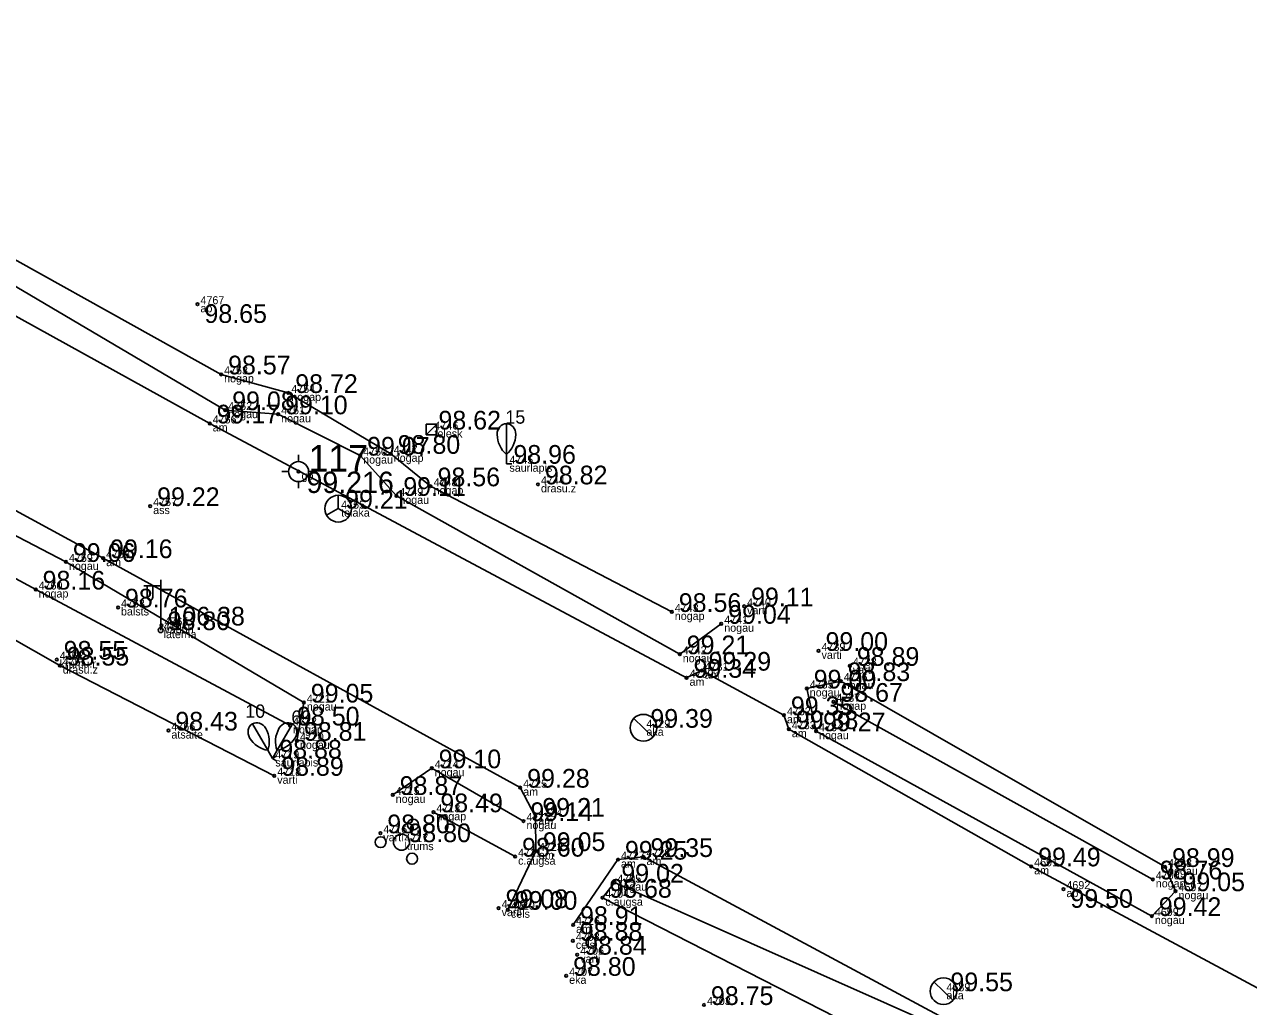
# Model space of a CAD drawing. Extents: x 614911 to 615803, y 262110 to 264311.
# Drawn here: x 615424.61 to 615470.48, y 264009.08 to 264045.87 of the extents above; entities that cross this region are included whole.
import ezdxf

# ---------------------------------------------------------------- set-up
doc = ezdxf.new("R2010")
doc.units = 0
for name, color, linetype in [('Level 1', 7, 'Continuous'), ('Level 12', 7, 'Continuous'), ('Level 19', 7, 'Continuous'), ('Level 31', 7, 'Continuous'), ('Level 35', 7, 'Continuous'), ('Level 37', 7, 'Continuous'), ('Level 44', 7, 'Continuous'), ('Level 49', 7, 'Continuous'), ('Level 53', 7, 'Continuous'), ('Level 54', 7, 'Continuous'), ('Level 57', 7, 'Continuous'), ('Level 58', 7, 'Continuous')]:
    doc.layers.add(name, color=color, linetype=linetype)

msp = doc.modelspace()

# ---------------------------------------------------------------- linework, layer by layer
at = {"layer": 'Level 1'}
for p, q in [((615442.676, 264029.765), (615442.676, 264029.413)), ((615442.676, 264029.413), (615442.876, 264029.413)), ((615433.728, 264018.676), (615433.904, 264018.371)), ((615434.08, 264018.676), (615433.904, 264018.371)), ((615433.904, 264018.371), (615434.077, 264018.471)), ((615433.904, 264018.371), (615434.077, 264018.271))]:
    msp.add_line(p, q, dxfattribs=at)
for points in [[(615442.676, 264030.913), (615442.676, 264029.765)], [(615433.154, 264019.67), (615433.728, 264018.676)], [(615434.654, 264019.67), (615434.08, 264018.676)]]:
    msp.add_lwpolyline(points, dxfattribs=at)
for centre, radius in [((615439.17, 264015.896), 0.207), ((615437.959, 264015.236), 0.204), ((615438.743, 264015.236), 0.301), ((615439.138, 264014.616), 0.205)]:
    msp.add_circle(centre, radius, dxfattribs=at)
for centre, major_axis, start_param, end_param in [((615442.676, 264030.513), (0, 0.4), 0, 1.570796), ((615442.676, 264030.513), (0, -0.4), 1.570796, 3.141593), ((615443.151, 264030.536), (0, -0.943), 4.7372, 5.669711), ((615442.201, 264030.536), (0, -0.943), 0.613474, 1.545985), ((615433.354, 264019.324), (-0.2, 0.346), 0, 1.570796), ((615433.354, 264019.324), (0.2, -0.346), 1.570796, 3.141593), ((615432.931, 264019.106), (0.472, -0.817), 0.613474, 1.545985), ((615434.877, 264019.106), (-0.472, -0.817), 4.7372, 5.669711), ((615434.454, 264019.324), (0.2, 0.346), 0, 1.570796), ((615434.454, 264019.324), (-0.2, -0.346), 1.570796, 3.141593), ((615433.754, 264019.582), (0.472, -0.817), 4.7372, 5.669711), ((615434.054, 264019.582), (-0.472, -0.817), 0.613474, 1.545985)]:
    msp.add_ellipse(centre, major_axis=major_axis, ratio=0.875, start_param=start_param, end_param=end_param, dxfattribs=at)
at = {"layer": 'Level 12'}
for p, q in [((615447.449, 264019.871), (615448.167, 264019.175)), ((615458.693, 264009.999), (615459.411, 264009.303))]:
    msp.add_line(p, q, dxfattribs=at)
for centre in [(615447.808, 264019.523), (615459.052, 264009.651)]:
    msp.add_circle(centre, 0.5, dxfattribs=at)
at = {"layer": 'Level 19'}
for p, q in [((615434.885, 264029.492), (615434.885, 264029.742)), ((615434.26, 264029.117), (615434.51, 264029.117)), ((615435.26, 264029.117), (615435.51, 264029.117)), ((615434.885, 264028.492), (615434.885, 264028.742))]:
    msp.add_line(p, q, dxfattribs=at)
for radius in [0.375, 0.05]:
    msp.add_circle((615434.885, 264029.117), radius, dxfattribs=at)
at = {"layer": 'Level 31'}
for p, q in [((615454.928, 264020.495), (615466.895, 264013.841)), ((615439.939, 264016.356), (615442.999, 264014.693)), ((615446.72, 264013.721), (615446.269, 264013.155))]:
    msp.add_line(p, q, dxfattribs=at)
for points in [[(615386.263, 264042.093), (615388.337, 264043.983), (615391.47, 264044.363), (615406.198, 264036.123), (615426.169, 264025.735), (615435.084, 264020.467), (615434.826, 264019.032)], [(615434.567, 264019.609), (615425.034, 264024.7), (615405.647, 264035.19), (615390.364, 264043.193), (615388.252, 264042.985), (615387.189, 264041.741)], [(615450.725, 264023.418), (615449.171, 264022.277), (615438.55, 264028.209), (615437.195, 264029.718), (615434.121, 264031.266), (615432.138, 264031.421), (615420.658, 264038.184), (615421.393, 264039.692)], [(615420.949, 264038.905), (615431.984, 264032.762), (615434.501, 264032.064), (615438.34, 264029.785), (615439.834, 264028.568), (615448.872, 264023.861)], [(615438.415, 264017.007), (615439.875, 264018.004), (615443.314, 264016.027)], [(615446.72, 264013.721), (615459.445, 264008.063), (615466.439, 264003.929), (615481.175, 263995.705), (615483.48, 263994.473)], [(615483.118, 263993.635), (615480.696, 263994.875), (615465.804, 264002.777), (615457.185, 264007.567), (615446.269, 264013.155)]]:
    msp.add_lwpolyline(points, dxfattribs=at)
msp.add_lwpolyline([(615455.202, 264021.269), (615453.929, 264020.994), (615454.276, 264019.392), (615466.861, 264012.469), (615467.747, 264013.399), (615467.356, 264014.307)], close=True, dxfattribs=at)
at = {"layer": 'Level 35'}
msp.add_lwpolyline([(615433.976, 264017.723), (615425.938, 264021.851), (615408.521, 264031.765), (615388.586, 264042.244)], dxfattribs=at)
at = {"layer": 'Level 37'}
for points in [[(615384.37, 264042.377), (615385.646, 264044.2), (615388.911, 264045.581), (615390.692, 264045.869), (615406.848, 264037.123), (615427.562, 264025.876), (615443.192, 264017.278), (615443.759, 264016.189), (615443.78, 264014.904), (615442.731, 264012.703)], [(615505.246, 263991.346), (615490.236, 263999.257), (615489.731, 263999.646), (615489.58, 264000.276), (615489.315, 264000.521), (615486.62, 264001.883), (615485.756, 264001.708), (615471.478, 264009.412), (615462.339, 264014.329), (615453.258, 264019.469), (615453.074, 264019.991), (615449.99, 264021.661), (615449.426, 264021.395), (615431.556, 264030.923), (615420.286, 264037.155), (615419.751, 264038.201), (615421.27, 264041.035)], [(615445.172, 264012.133), (615446.855, 264014.581), (615447.812, 264014.681), (615467.756, 264003.972), (615471.133, 264003.004), (615482.8, 263995.731), (615497.199, 263988.006), (615497.443, 263987.306), (615497.175, 263986.862), (615496.824, 263987.044), (615495.619, 263984.912), (615496.084, 263984.596)]]:
    msp.add_lwpolyline(points, dxfattribs=at)
at = {"layer": 'Level 44'}
for p, q in [((615429.718, 264023.179), (615429.718, 264025.062)), ((615429.718, 264024.842), (615429.083, 264024.842)), ((615429.218, 264024.842), (615429.218, 264024.45)), ((615429.428, 264024.842), (615429.428, 264024.45))]:
    msp.add_line(p, q, dxfattribs=at)
msp.add_circle((615429.718, 264023.179), 0.09, dxfattribs=at)
msp.add_ellipse((615429.323, 264024.45), major_axis=(0, 0.151), ratio=0.695971, start_param=1.570796, end_param=4.712389, dxfattribs=at)
at = {"layer": 'Level 49'}
for p, q in [((615439.666, 264030.498), (615439.666, 264030.892)), ((615439.666, 264030.892), (615440.068, 264030.892)), ((615436.371, 264028.23), (615436.371, 264027.73)), ((615435.938, 264027.48), (615436.371, 264027.73)), ((615436.371, 264027.73), (615436.804, 264027.48))]:
    msp.add_line(p, q, dxfattribs=at)
msp.add_lwpolyline([(615439.666, 264030.498), (615440.068, 264030.892), (615440.068, 264030.498)], close=True, dxfattribs=at)
msp.add_circle((615436.371, 264027.73), 0.5, dxfattribs=at)
at = {"layer": 'Level 57'}
for centre in [(615431.098, 264035.389), (615431.984, 264032.762), (615434.501, 264032.064), (615432.138, 264031.421), (615431.556, 264030.923), (615434.121, 264031.266), (615437.195, 264029.718), (615438.34, 264029.785), (615439.834, 264028.568), (615443.857, 264028.641), (615438.55, 264028.209), (615429.325, 264027.827), (615427.562, 264025.876), (615426.169, 264025.735), (615425.034, 264024.7), (615428.12, 264024.029), (615451.581, 264024.071), (615448.872, 264023.861), (615429.75, 264023.353), (615450.725, 264023.418), (615449.171, 264022.277), (615454.371, 264022.403), (615425.823, 264022.073), (615425.938, 264021.851), (615449.99, 264021.661), (615455.545, 264021.843), (615449.426, 264021.395), (615455.202, 264021.269), (615453.929, 264020.994), (615435.084, 264020.467), (615454.928, 264020.495), (615453.074, 264019.991), (615430.008, 264019.417), (615434.567, 264019.609), (615453.258, 264019.469), (615454.276, 264019.392), (615434.826, 264019.032), (615439.875, 264018.004), (615433.976, 264017.723), (615443.192, 264017.278), (615438.415, 264017.007), (615439.939, 264016.356), (615443.759, 264016.189), (615443.314, 264016.027), (615437.95, 264015.569), (615443.78, 264014.904), (615442.999, 264014.693), (615446.855, 264014.581), (615447.812, 264014.681), (615462.339, 264014.329), (615467.356, 264014.307), (615446.72, 264013.721), (615463.547, 264013.477), (615466.895, 264013.841), (615446.269, 264013.155), (615467.747, 264013.399), (615442.383, 264012.764), (615442.731, 264012.703), (615445.172, 264012.133), (615466.861, 264012.469), (615445.165, 264011.539), (615445.328, 264011.02), (615444.914, 264010.229), (615450.077, 264009.136)]:
    msp.add_circle(centre, 0.05, dxfattribs=at)
at = {"layer": 'Level 58'}
for centre in [(615431.098, 264035.389), (615431.984, 264032.762), (615434.501, 264032.064), (615432.138, 264031.421), (615431.556, 264030.923), (615434.121, 264031.266), (615437.195, 264029.718), (615438.34, 264029.785), (615439.834, 264028.568), (615443.857, 264028.641), (615438.55, 264028.209), (615429.325, 264027.827), (615427.562, 264025.876), (615426.169, 264025.735), (615425.034, 264024.7), (615428.12, 264024.029), (615451.581, 264024.071), (615448.872, 264023.861), (615429.75, 264023.353), (615450.725, 264023.418), (615449.171, 264022.277), (615454.371, 264022.403), (615425.823, 264022.073), (615425.938, 264021.851), (615449.99, 264021.661), (615455.545, 264021.843), (615449.426, 264021.395), (615455.202, 264021.269), (615453.929, 264020.994), (615435.084, 264020.467), (615454.928, 264020.495), (615453.074, 264019.991), (615430.008, 264019.417), (615434.567, 264019.609), (615453.258, 264019.469), (615454.276, 264019.392), (615434.826, 264019.032), (615439.875, 264018.004), (615433.976, 264017.723), (615443.192, 264017.278), (615438.415, 264017.007), (615439.939, 264016.356), (615443.759, 264016.189), (615443.314, 264016.027), (615437.95, 264015.569), (615443.78, 264014.904), (615442.999, 264014.693), (615446.855, 264014.581), (615447.812, 264014.681), (615462.339, 264014.329), (615467.356, 264014.307), (615446.72, 264013.721), (615463.547, 264013.477), (615466.895, 264013.841), (615446.269, 264013.155), (615467.747, 264013.399), (615442.383, 264012.764), (615442.731, 264012.703), (615445.172, 264012.133), (615466.861, 264012.469), (615445.165, 264011.539), (615445.328, 264011.02), (615444.914, 264010.229), (615450.077, 264009.136)]:
    msp.add_circle(centre, 0.05, dxfattribs=at)

# ---------------------------------------------------------------- texts
at = {"layer": 'Level 1'}
for s, p in [(' 15', (615442.451, 264030.913)), (' 10', (615432.704, 264019.895)), (' 69', (615434.429, 264019.67))]:
    msp.add_text(s, height=0.5, dxfattribs=at).set_placement(p)
at = {"layer": 'Level 19'}
for s, height, p in [(' 117', 1, (615434.885, 264029.117)), (' 99.216', 0.8, (615434.885, 264028.317))]:
    msp.add_text(s, height=height, dxfattribs=at).set_placement(p)
at = {"layer": 'Level 49'}
msp.add_text(' 99.21', height=0.7, dxfattribs=at).set_placement((615436.371, 264027.73))
at = {"layer": 'Level 53'}
for s, p in [(' ap', (615431.098, 264035.089)), (' nogap', (615431.984, 264032.462)), (' nogap', (615434.501, 264031.764)), (' nogau', (615432.138, 264031.121)), (' nogau', (615434.121, 264030.966)), (' am', (615431.556, 264030.623)), (' telesk', (615439.867, 264030.395)), (' nogau', (615437.195, 264029.418)), (' nogap', (615438.34, 264029.485)), (' gp', (615434.885, 264028.817)), (' saurlapis', (615442.676, 264029.113)), (' drasu.z', (615443.857, 264028.341)), (' nogau', (615438.55, 264027.909)), (' nogap', (615439.834, 264028.268)), (' ass', (615429.325, 264027.527)), (' telaka', (615436.371, 264027.43)), (' nogau', (615426.169, 264025.435)), (' am', (615427.562, 264025.576)), (' nogap', (615425.034, 264024.4)), (' balsts', (615428.12, 264023.729)), (' varti', (615451.581, 264023.771)), (' nogap', (615448.872, 264023.561)), (' laterna', (615429.718, 264022.879)), (' vaduh', (615429.75, 264023.053)), (' nogau', (615450.725, 264023.118)), (' nogau', (615449.171, 264021.977)), (' varti', (615454.371, 264022.103)), (' krumu.r', (615425.823, 264021.773)), (' drasu.z', (615425.938, 264021.551)), (' varti', (615455.545, 264021.543)), (' am', (615449.426, 264021.095)), (' am', (615449.99, 264021.361)), (' nogau', (615453.929, 264020.694)), (' nogau', (615455.202, 264020.969)), (' nogau', (615435.084, 264020.167)), (' nogap', (615454.928, 264020.195)), (' am', (615453.074, 264019.691)), (' atsaite', (615430.008, 264019.117)), (' nogap', (615434.567, 264019.309)), (' aka', (615447.808, 264019.223)), (' nogau', (615434.826, 264018.732)), (' am', (615453.258, 264019.169)), (' nogau', (615454.276, 264019.092)), (' saurlapis', (615433.904, 264018.071)), (' varti', (615433.976, 264017.423)), (' nogau', (615439.875, 264017.704)), (' am', (615443.192, 264016.978)), (' nogau', (615438.415, 264016.707)), (' nogap', (615439.939, 264016.056)), (' nogau', (615443.314, 264015.727)), (' am', (615443.759, 264015.889)), (' varti', (615437.95, 264015.269)), (' krums', (615438.743, 264014.936)), (' am', (615443.78, 264014.604)), (' c.augsa', (615442.999, 264014.393)), (' am', (615446.855, 264014.281)), (' am', (615447.812, 264014.381)), (' am', (615462.339, 264014.029)), (' nogau', (615467.356, 264014.007)), (' nogau', (615446.72, 264013.421)), (' nogap', (615466.895, 264013.541)), (' c.augsa', (615446.269, 264012.855)), (' ap', (615463.547, 264013.177)), (' nogau', (615467.747, 264013.099)), (' varti', (615442.383, 264012.464)), (' cels', (615442.731, 264012.403)), (' nogau', (615466.861, 264012.169)), (' am', (615445.172, 264011.833)), (' cels', (615445.165, 264011.239)), (' varti', (615445.328, 264010.72)), (' eka', (615444.914, 264009.929)), (' aka', (615459.052, 264009.351))]:
    msp.add_text(s, height=0.3, dxfattribs=at).set_placement(p)
at = {"layer": 'Level 54'}
for s, p in [(' 4767', (615431.098, 264035.389)), (' 4753', (615431.984, 264032.762)), (' 4754', (615434.501, 264032.064)), (' 4752', (615432.138, 264031.421)), (' 4751', (615434.121, 264031.266)), (' 4756', (615431.556, 264030.923)), (' 4746', (615439.867, 264030.695)), (' 4750', (615437.195, 264029.718)), (' 4747', (615438.34, 264029.785)), (' 4745', (615442.676, 264029.413)), (' 4748', (615439.834, 264028.568)), (' 4744', (615443.857, 264028.641)), (' 4749', (615438.55, 264028.209)), (' 4757', (615429.325, 264027.827)), (' 4755', (615436.371, 264027.73)), (' 4759', (615426.169, 264025.735)), (' 4758', (615427.562, 264025.876)), (' 4760', (615425.034, 264024.7)), (' 4763', (615428.12, 264024.029)), (' 4743', (615448.872, 264023.861)), (' 4740', (615451.581, 264024.071)), (' 4765', (615429.75, 264023.353)), (' 4741', (615450.725, 264023.418)), (' 4764', (615429.718, 264023.179)), (' 4739', (615454.371, 264022.403)), (' 4762', (615425.823, 264022.073)), (' 4742', (615449.171, 264022.277)), (' 4761', (615425.938, 264021.851)), (' 4731', (615449.99, 264021.661)), (' 4738', (615455.545, 264021.843)), (' 4730', (615449.426, 264021.395)), (' 4735', (615453.929, 264020.994)), (' 4736', (615455.202, 264021.269)), (' 4737', (615454.928, 264020.495)), (' 4721', (615435.084, 264020.467)), (' 4722', (615434.567, 264019.609)), (' 4732', (615453.074, 264019.991)), (' 4766', (615430.008, 264019.417)), (' 4729', (615447.808, 264019.523)), (' 4733', (615453.258, 264019.469)), (' 4734', (615454.276, 264019.392)), (' 4720', (615434.826, 264019.032)), (' 4719', (615433.904, 264018.371)), (' 4714', (615439.875, 264018.004)), (' 4718', (615433.976, 264017.723)), (' 4725', (615443.192, 264017.278)), (' 4715', (615438.415, 264017.007)), (' 4713', (615439.939, 264016.356)), (' 4712', (615443.314, 264016.027)), (' 4724', (615443.759, 264016.189)), (' 4716', (615437.95, 264015.569)), (' 4717', (615438.743, 264015.236)), (' 4711', (615442.999, 264014.693)), (' 4723', (615443.78, 264014.904)), (' 4727', (615446.855, 264014.581)), (' 4728', (615447.812, 264014.681)), (' 4691', (615462.339, 264014.329)), (' 4698', (615467.356, 264014.307)), (' 4705', (615446.72, 264013.721)), (' 4700', (615466.895, 264013.841)), (' 4704', (615446.269, 264013.155)), (' 4692', (615463.547, 264013.477)), (' 4697', (615467.747, 264013.399)), (' 4709', (615442.383, 264012.764)), (' 4710', (615442.731, 264012.703)), (' 4699', (615466.861, 264012.469)), (' 4726', (615445.172, 264012.133)), (' 4708', (615445.165, 264011.539)), (' 4706', (615445.328, 264011.02)), (' 4707', (615444.914, 264010.229)), (' 4689', (615459.052, 264009.651)), (' 4703', (615450.077, 264009.136))]:
    msp.add_text(s, height=0.3, dxfattribs=at).set_placement(p)
at = {"layer": 'Level 58'}
for s, p in [(' 98.65', (615431.098, 264034.689)), (' 98.57', (615431.984, 264032.762)), (' 98.72', (615434.501, 264032.064)), (' 99.08', (615432.138, 264031.421)), (' 99.10', (615434.121, 264031.266)), (' 99.17', (615431.556, 264030.923)), (' 98.62', (615439.867, 264030.695)), (' 99.07', (615437.195, 264029.718)), (' 98.80', (615438.34, 264029.785)), (' 98.96', (615442.676, 264029.413)), (' 98.56', (615439.834, 264028.568)), (' 98.82', (615443.857, 264028.641)), (' 99.11', (615438.55, 264028.209)), (' 99.22', (615429.325, 264027.827)), (' 99.06', (615426.169, 264025.735)), (' 99.16', (615427.562, 264025.876)), (' 98.16', (615425.034, 264024.7)), (' 98.76', (615428.12, 264024.029)), (' 98.56', (615448.872, 264023.861)), (' 99.11', (615451.581, 264024.071)), (' 106.38', (615429.75, 264023.353)), (' 99.04', (615450.725, 264023.418)), (' 98.80', (615429.718, 264023.179)), (' 99.00', (615454.371, 264022.403)), (' 98.55', (615425.823, 264022.073)), (' 99.21', (615449.171, 264022.277)), (' 98.55', (615425.938, 264021.851)), (' 99.29', (615449.99, 264021.661)), (' 98.89', (615455.545, 264021.843)), (' 99.34', (615449.426, 264021.395)), (' 98.83', (615455.202, 264021.269)), (' 99.00', (615453.929, 264020.994)), (' 99.05', (615435.084, 264020.467)), (' 98.67', (615454.928, 264020.495)), (' 99.35', (615453.074, 264019.991)), (' 98.43', (615430.008, 264019.417)), (' 98.50', (615434.567, 264019.609)), (' 99.39', (615447.808, 264019.523)), (' 99.38', (615453.258, 264019.469)), (' 99.27', (615454.276, 264019.392)), (' 98.81', (615434.826, 264019.032)), (' 98.88', (615433.904, 264018.371)), (' 99.10', (615439.875, 264018.004)), (' 98.89', (615433.976, 264017.723)), (' 98.87', (615438.415, 264017.007)), (' 99.28', (615443.192, 264017.278)), (' 98.49', (615439.939, 264016.356)), (' 99.14', (615443.314, 264016.027)), (' 99.21', (615443.759, 264016.189)), (' 98.80', (615437.95, 264015.569)), (' 98.80', (615438.743, 264015.236)), (' 98.60', (615442.999, 264014.693)), (' 99.05', (615443.78, 264014.904)), (' 99.25', (615446.855, 264014.581)), (' 99.35', (615447.812, 264014.681)), (' 99.49', (615462.339, 264014.329)), (' 98.99', (615467.356, 264014.307)), (' 99.02', (615446.72, 264013.721)), (' 98.76', (615466.895, 264013.841)), (' 99.05', (615467.747, 264013.399)), (' 99.08', (615442.383, 264012.764)), (' 98.68', (615446.269, 264013.155)), (' 99.50', (615463.547, 264012.777)), (' 99.00', (615442.731, 264012.703)), (' 99.42', (615466.861, 264012.469)), (' 98.91', (615445.172, 264012.133)), (' 98.88', (615445.165, 264011.539)), (' 98.84', (615445.328, 264011.02)), (' 98.80', (615444.914, 264010.229)), (' 99.55', (615459.052, 264009.651)), (' 98.75', (615450.077, 264009.136))]:
    msp.add_text(s, height=0.7, dxfattribs=at).set_placement(p)

doc.saveas('drawing.dxf')
